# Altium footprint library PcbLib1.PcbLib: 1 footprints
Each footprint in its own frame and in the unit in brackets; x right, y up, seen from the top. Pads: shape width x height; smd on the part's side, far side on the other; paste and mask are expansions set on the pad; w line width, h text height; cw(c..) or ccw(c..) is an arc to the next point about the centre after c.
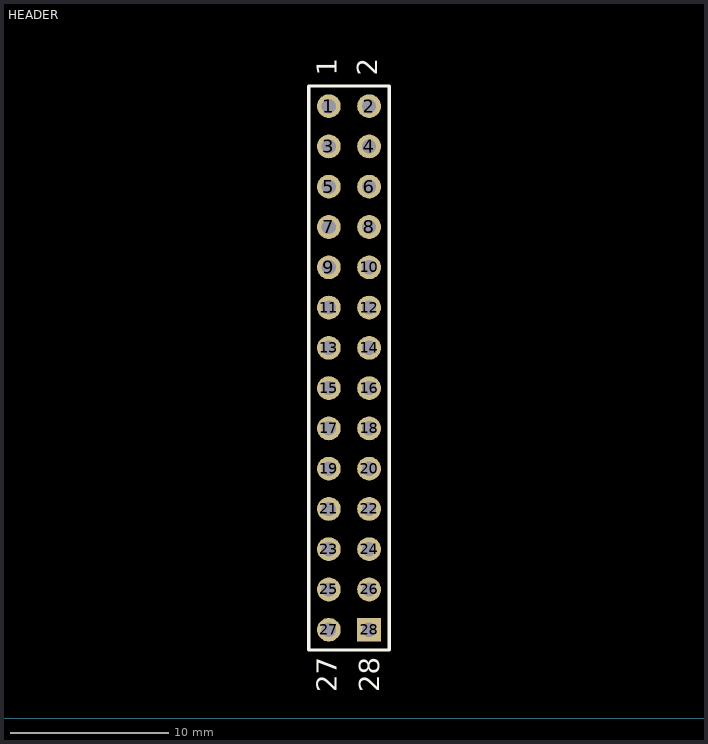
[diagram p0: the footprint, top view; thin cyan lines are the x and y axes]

## HEADER [mm]
pads (28):
  round 1.5 hole 0.9: 1(31.623,38.608) 2(34.163,38.608) 3(31.623,36.068) 4(34.163,36.068) 5(31.623,33.528) 6(34.163,33.528) 7(31.623,30.988) 8(34.163,30.988) 9(31.623,28.448) 10(34.163,28.448) 11(31.623,25.908) 12(34.163,25.908) 13(31.623,23.368) 14(34.163,23.368) 15(31.623,20.828) 16(34.163,20.828) 17(31.623,18.288) 18(34.163,18.288) 19(31.623,15.748) 20(34.163,15.748) 21(31.623,13.208) 22(34.163,13.208) 23(31.623,10.668) 24(34.163,10.668) 25(31.623,8.128) 26(34.163,8.128) 27(31.623,5.588)
  rect 1.5x1.5 hole 0.9: 28(34.163,5.588)
Top Overlay:
  lines w0.2: 30.353,4.318 30.353,39.878 35.433,39.878 35.433,4.318 30.353,4.318
  text "27" at 32.131,1.651 h1.27
  text "28" at 34.798,1.651 h1.27
  text "2" at 34.671,40.513 h1.27
  text "1" at 32.131,40.513 h1.27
